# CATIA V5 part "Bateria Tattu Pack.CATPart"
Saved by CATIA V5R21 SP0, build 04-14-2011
Part number: Bateria Tattu Pack
Material "DS Red": density 7860 kg/m3, Young's modulus 2e+11 Pa, Poisson ratio 0.266
Bounding box of the stored display mesh (mm): x 173.5 to 386.5, y 42.5 to 111.5, z -48 to 48
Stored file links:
  C:\Users\rodri\OneDrive\Área de Trabalho\FACULDADE\3°semestre\Sistemas Aeroespaciais\Projeto de avião 2019-02\CAD\Bateria Tattu Pack.CATPart
  C:\Program Files (x86)\Dassault Systemes\B21\intel_a\startup\materials\red_env_512x512.jpg
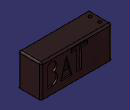
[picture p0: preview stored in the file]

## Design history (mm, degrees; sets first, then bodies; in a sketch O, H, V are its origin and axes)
Body1 (main body), material "DS Red"
  Sketch1 on yz-plane, origin (0, 0, 0), H (0, 1, 0), V (0, 0, 1)
    line L1 (-106.5, 48) -> (106.5, 48)
    line L2 (106.5, 48) -> (106.5, -48)
    line L3 (106.5, -48) -> (-106.5, -48)
    line L4 (-106.5, -48) -> (-106.5, 48)
    distance L4 L2 = 213
    distance L3 L1 = 96
    horizontal: L1 H, L3 H
    vertical: L2 V, L4 V
    symmetry: L4 L2 V, L3 L1 H
  Pad1: profile Sketch1, direction (1, 0, 0), length 34.5, mirrored extent
  Fillet1: radius 5, on edge [face of Pad1 from Sketch1.L1 | face of Pad1 from Sketch1.L2]
  Fillet2: radius 5, on edge [face of Pad1 from Sketch1.L2 | end face of Pad1]; edge [face of Pad1 from Sketch1.L1 | end face of Pad1]; edge [start face of Pad1 | face of Pad1 from Sketch1.L1]; edge [face of Pad1 from Sketch1.L4 | face of Pad1 from Sketch1.L1]; edge [face of Pad1 from Sketch1.L4 | end face of Pad1]; edge [start face of Pad1 | face of Pad1 from Sketch1.L2]
  Fillet3: radius 5, on edge [start face of Pad1 | face of Pad1 from Sketch1.L4]
  Sketch2 on face of Pad1 from Sketch1.L1, origin (0, 0, 48), H (1, 0, 0), V (0, 1, 0)
    circle A1 centre (-14.5, -90) radius 5
    point P1 (-14.5, -90)
    circle A2 centre (14.5, -90) radius 5
    point P2 (14.5, -90)
    reference projected line E1 (-34.5, 101.5) -> (-34.5, -106.5) from edge [start face of Pad1 | face of Fillet2]
    distance P1 E1 = 20
    radius A1 = 5
    radius A2 = 5
    distance A2 H = 85
    symmetry: P1 P2 V
  Pocket1: profile Sketch2, direction (0, 0, -1), length 10
  Sketch3 on start face of Pad1, origin (-34.5, 0, 0), H (0, -1, 0), V (0, 0, 1)
    line L1 (-86.2435, -27.0111) -> (-86.2435, 30.4896)
    arc A1 centre (-73.5977, 21.6671) radius 15.4193 from (-86.2435, 30.4896) to (-68.3938, 7.1525) cw
    arc A2 centre (-74.0974, -9.6616) radius 17.7552 from (-68.3938, 7.1525) to (-70.3235, -27.0111) cw
    line L2 (-70.3235, -27.0111) -> (-86.2435, -27.0111)
    point P7 (-46.9259, -27.0111)
    line L3 (-46.9259, -27.0111) -> (-30.0411, 30.4896)
    line L4 (-30.0411, 30.4896) -> (-13.3975, -27.0111)
    point P9 (-13.3975, -27.0111)
    line L5 (-13.3975, -27.0111) -> (-46.9259, -27.0111)
    point P10 (-37.5187, 0)
    line L6 (-37.5187, 0) -> (-23.046, 0)
    line L7 (-23.046, 0) -> (-23.046, -5.3581)
    line L8 (-23.046, -5.3581) -> (-37.5187, -5.3581)
    line L9 (-37.5187, -5.3581) -> (-37.5187, 0)
    point P14 (0, 30.4896)
    line L10 (0, 30.4896) -> (0, -27.0111)
    point P15 (0, -27.0111)
    line L11 (0, -27.0111) -> (14.58, -26.9312)
    line L12 (14.58, -26.9312) -> (14.2654, 30.4896)
    line L13 (14.2654, 30.4896) -> (32.674, 30.4896)
    line L14 (32.674, 30.4896) -> (32.674, 40.1131)
    line L15 (32.674, 40.1131) -> (-15.086, 40.1131)
    line L16 (-15.086, 40.1131) -> (-15.086, 30.4896)
    point P21 (-15.086, 30.4896)
    line L17 (-15.086, 30.4896) -> (0, 30.4896)
    vertical: L1 V, L7 V, L9 V, L10 V, L14 V, L16 V
    horizontal: L2 H, L5 H, L6 H, L8 H, L13 H, L15 H, L17 H
    coincidence: P7 L2, P9 L2, P10 H, P14 V, P15 L2, P21 L13
    tangency: L11 A2
  Pocket2: profile Sketch3, direction (1, 0, 0), length 5
  Sketch4 on end face of Pad1, origin (34.5, 0, 0), H (0, 1, 0), V (0, 0, 1)
    axis line L1 (-201.212, 0) -> (227.9274, 0)
    point P1 (-201.212, 0)
    coincidence: P1 H
    horizontal: L1 H
  Rotate1: Axis edge [start face of Pad1 | face of Fillet2], Angle 90, ToTransfor Pocket2
  Rotate2: Axis edge [face of Pad1 from Sketch1.L4 | face of Fillet3], Angle 90, ToTransfor Rotate1
  Rotate3: Axis edge [face of Pad1 from Sketch1.L4 | face of Fillet3], Angle 90, ToTransfor Rotate2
